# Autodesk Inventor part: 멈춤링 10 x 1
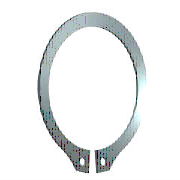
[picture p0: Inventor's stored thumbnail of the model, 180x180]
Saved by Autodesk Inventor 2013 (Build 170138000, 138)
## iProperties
IsCustomPart: 0
Company: 한국ATC센터
Created: 2014-07
Part Number: 멈춤링 10 x 1
Material: Steel, Mild
Description: 리테이닝 링(C형)
Document SubType Name: Modeling
Standard: KS B 1336
Designer: KYOUNG IL JANG
Standards Organization: KS
Language: ko-KR
Size Designation: 10 x 1
Categories: <MemberInstance><Categories><Category DisplayName="샤프트 부품" InternalName="7f7aeb1f-a693-4053-b835-cee3144e0d98" Mnemonic="SHFT"><Category DisplayName="써클립" Inter
Density: 7.86 g/cm^3
Mass: 0.423084 g
Surface Area: 1.9243 cm^2
Volume: 0.0538275 cm^3
Author: KYOUNG IL JANG
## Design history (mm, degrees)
sketch "스케치1"
  geometry: L1 (-6, 0)-(6, 0) reference; L2 (0, 20.189)-(0, -80.536) reference; L3 (-48.09, 0)-(48.09, 0) reference; L4 (-0.3, -9.791)-(-0.3, -12.791); L5 (-0.3, -6.54)-(-0.3, -13.29); L6 (-2.795, 1.6)-(3.672, 1.6); L7 (0.3, -6.54)-(0.3, -13.29); L8 (0.3, -9.791)-(0.3, -12.791); C1 r 0.6 at (-1.2, -11.486); C2 r 0.6 at (1.2, -11.486); A1 r 4.8 centre (0, -5) between (0.3, -9.791) and (-0.3, -9.791); A2 r 6.2 centre (0, -4.6) between (2.988, -10.033) and (-2.988, -10.033); A3 r 7.796 centre (0, -5) between (-1.418, -12.666) and (-0.3, -12.791); A4 r 1.2 centre (-1.2, -11.486) between (-2.383, -11.285) and (-1.418, -12.666); A5 r 1.2 centre (-3.566, -11.084) between (-2.383, -11.285) and (-2.988, -10.033); A6 r 1.2 centre (3.566, -11.084) between (2.988, -10.033) and (2.383, -11.285); A7 r 1.2 centre (1.2, -11.486) between (1.418, -12.666) and (2.383, -11.285); A8 r 7.796 centre (0, -5) between (0.3, -12.791) and (1.418, -12.666)
  constraints: 16 point on circle, 12 end point, 10 centre point, 9 symmetric about line, 5 point on line, 4 tangent, 3 coincident, 2 horizontal, 1 perpendicular, 1 vertical, 5 other
  dimensions: "d0" = 9.6 diameter of A1 (= ND); "d1" = 3 distance of L4.end L4.start (= SRB2); "d6" = 0.3 distance between parallel lines of L2 L5 (= 0.25 x SD5); "d7" = 1.6 distance between parallel lines of L6 L3 (= SRB1); "d8" = 0.4 distance of A1.centre A2.centre (= 0.25 x SRB1); "d9" = 1.2 radius of A4 (= SD5); "d10" = 1.2 radius of A5 (= SD5); "d11" = 0.9 distance from line of L4 A4.centre (= 0.75 x SD5); "d12" = 1.2 diameter of C1 (= SD5); "d13" = 1.2 diameter of C2 (= SD5); "d14" = 5 distance from line of A1.centre L1 (= 0.5 x WD)
extrude "본체" new body sketch "스케치1" distance "d2" = 1 (= SD); taper "d3" = 0 deg
workaxis "Work Axis1"
workplane "Work Plane1"
body "Solid1"
other parameters: "SD" = 1 [user parameter; used in 1 equation term], "SRB1" = 1.6 [user parameter; used in 2 equation terms], "ND" = 9.6 [user parameter; used in 1 equation term], "SRB2" = 3 [user parameter; used in 1 equation term], "SD5" = 1.2 [user parameter; used in 6 equation terms], "d15" = 0, "d16" = 0, "d17" = 0, "d41" = 0, "d42" = 0, "SD3" = 9.3 [user parameter], "WDMAX" = 11 [user parameter]
